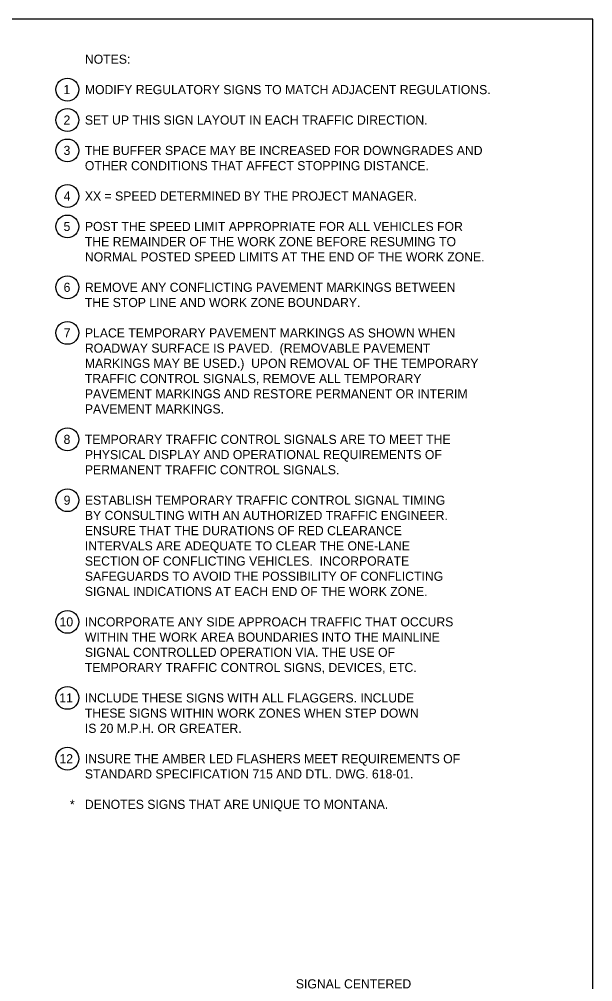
# Model space of a CAD drawing. Extents: x 49991.4 to 50021, y 49987.6 to 50011.4.
# Drawn here: x 50004.85 to 50008.61, y 50004.93 to 50011.26 of the extents above; entities that cross this region are included whole.
import ezdxf

# ---------------------------------------------------------------- set-up
doc = ezdxf.new("R2010")
doc.units = 0
doc.layers.add('Level 1', color=7, linetype='Continuous')
doc.layers.add('Level 2', color=7, linetype='Continuous')

msp = doc.modelspace()

# ---------------------------------------------------------------- linework, layer by layer
at = {"layer": 'Level 1'}
msp.add_lwpolyline([(50008.6146, 50011.2628), (50000.3356, 50011.2628), (50000.3356, 50000.0624), (50008.6146, 50000.0624)], close=True, dxfattribs=at)
at = {"layer": 'Level 2'}
for centre in [(50005.1633, 50010.8002), (50005.1633, 50010.6002), (50005.1633, 50010.4002), (50005.1633, 50010.1002), (50005.1633, 50009.9002), (50005.1633, 50009.5002), (50005.1633, 50009.2002), (50005.1633, 50008.5002), (50005.1633, 50008.1002), (50005.1633, 50007.3002), (50005.1633, 50006.8002), (50005.1633, 50006.4002)]:
    msp.add_circle(centre, 0.075, dxfattribs=at)

# ---------------------------------------------------------------- texts
for s, p in [('NOTES:', (50005.2783, 50010.9702)), ('1', (50005.137, 50010.7702)), ('MODIFY REGULATORY SIGNS TO MATCH ADJACENT REGULATIONS.', (50005.2783, 50010.7702)), ('2', (50005.1381, 50010.5702)), ('SET UP THIS SIGN LAYOUT IN EACH TRAFFIC DIRECTION.', (50005.2783, 50010.5702)), ('3', (50005.1381, 50010.3702)), ('THE BUFFER SPACE MAY BE INCREASED FOR DOWNGRADES AND ', (50005.2783, 50010.3702)), ('OTHER CONDITIONS THAT AFFECT STOPPING DISTANCE.', (50005.2783, 50010.2702)), ('4', (50005.1393, 50010.0702)), ('XX = SPEED DETERMINED BY THE PROJECT MANAGER.', (50005.2783, 50010.0702)), ('5', (50005.1383, 50009.8702)), ('POST THE SPEED LIMIT APPROPRIATE FOR ALL VEHICLES FOR ', (50005.2783, 50009.8702)), ('THE REMAINDER OF THE WORK ZONE BEFORE RESUMING TO ', (50005.2783, 50009.7702)), ('NORMAL POSTED SPEED LIMITS AT THE END OF THE WORK ZONE.', (50005.2783, 50009.6702)), ('6', (50005.1387, 50009.4702)), ('REMOVE ANY CONFLICTING PAVEMENT MARKINGS BETWEEN ', (50005.2783, 50009.4702)), ('THE STOP LINE AND WORK ZONE BOUNDARY.', (50005.2783, 50009.3702)), ('7', (50005.1395, 50009.1702)), ('PLACE TEMPORARY PAVEMENT MARKINGS AS SHOWN WHEN ', (50005.2783, 50009.1702)), ('ROADWAY SURFACE IS PAVED.  (REMOVABLE PAVEMENT ', (50005.2783, 50009.0702)), ('MARKINGS MAY BE USED.)  UPON REMOVAL OF THE TEMPORARY ', (50005.2783, 50008.9702)), ('TRAFFIC CONTROL SIGNALS, REMOVE ALL TEMPORARY ', (50005.2783, 50008.8702)), ('PAVEMENT MARKINGS AND RESTORE PERMANENT OR INTERIM ', (50005.2783, 50008.7702)), ('PAVEMENT MARKINGS.', (50005.2783, 50008.6702)), ('8', (50005.1383, 50008.4702)), ('TEMPORARY TRAFFIC CONTROL SIGNALS ARE TO MEET THE ', (50005.2783, 50008.4702)), ('PHYSICAL DISPLAY AND OPERATIONAL REQUIREMENTS OF ', (50005.2783, 50008.3702)), ('PERMANENT TRAFFIC CONTROL SIGNALS.', (50005.2783, 50008.2702)), ('9', (50005.1387, 50008.0702)), ('ESTABLISH TEMPORARY TRAFFIC CONTROL SIGNAL TIMING ', (50005.2783, 50008.0702)), ('BY CONSULTING WITH AN AUTHORIZED TRAFFIC ENGINEER.  ', (50005.2783, 50007.9702)), ('ENSURE THAT THE DURATIONS OF RED CLEARANCE ', (50005.2783, 50007.8702)), ('INTERVALS ARE ADEQUATE TO CLEAR THE ONE-LANE ', (50005.2783, 50007.7702)), ('SECTION OF CONFLICTING VEHICLES.  INCORPORATE ', (50005.2783, 50007.6702)), ('SAFEGUARDS TO AVOID THE POSSIBILITY OF CONFLICTING ', (50005.2783, 50007.5702)), ('SIGNAL INDICATIONS AT EACH END OF THE WORK ZONE.', (50005.2783, 50007.4702)), ('10', (50005.1119, 50007.2702)), ('INCORPORATE ANY SIDE APPROACH TRAFFIC THAT OCCURS ', (50005.2783, 50007.2702)), ('WITHIN THE WORK AREA BOUNDARIES INTO THE MAINLINE ', (50005.2783, 50007.1702)), ('SIGNAL CONTROLLED OPERATION VIA. THE USE OF ', (50005.2783, 50007.0702)), ('TEMPORARY TRAFFIC CONTROL SIGNS, DEVICES, ETC.', (50005.2783, 50006.9702)), ('11', (50005.11, 50006.7702)), ('INCLUDE THESE SIGNS WITH ALL FLAGGERS. INCLUDE ', (50005.2783, 50006.7702)), ('THESE SIGNS WITHIN WORK ZONES WHEN STEP DOWN', (50005.2783, 50006.6702)), ('IS 20 M.P.H. OR GREATER.', (50005.2783, 50006.5702)), ('12', (50005.1112, 50006.3702)), ('INSURE THE AMBER LED FLASHERS MEET REQUIREMENTS OF', (50005.2783, 50006.3702)), ('STANDARD SPECIFICATION 715 AND DTL. DWG. 618-01.', (50005.2783, 50006.2702)), ('*', (50005.1797, 50006.0702)), ('DENOTES SIGNS THAT ARE UNIQUE TO MONTANA.', (50005.2783, 50006.0702)), ('SIGNAL CENTERED', (50006.6642, 50004.8899))]:
    msp.add_text(s, height=0.06, dxfattribs=at).set_placement(p)

doc.saveas('drawing.dxf')
